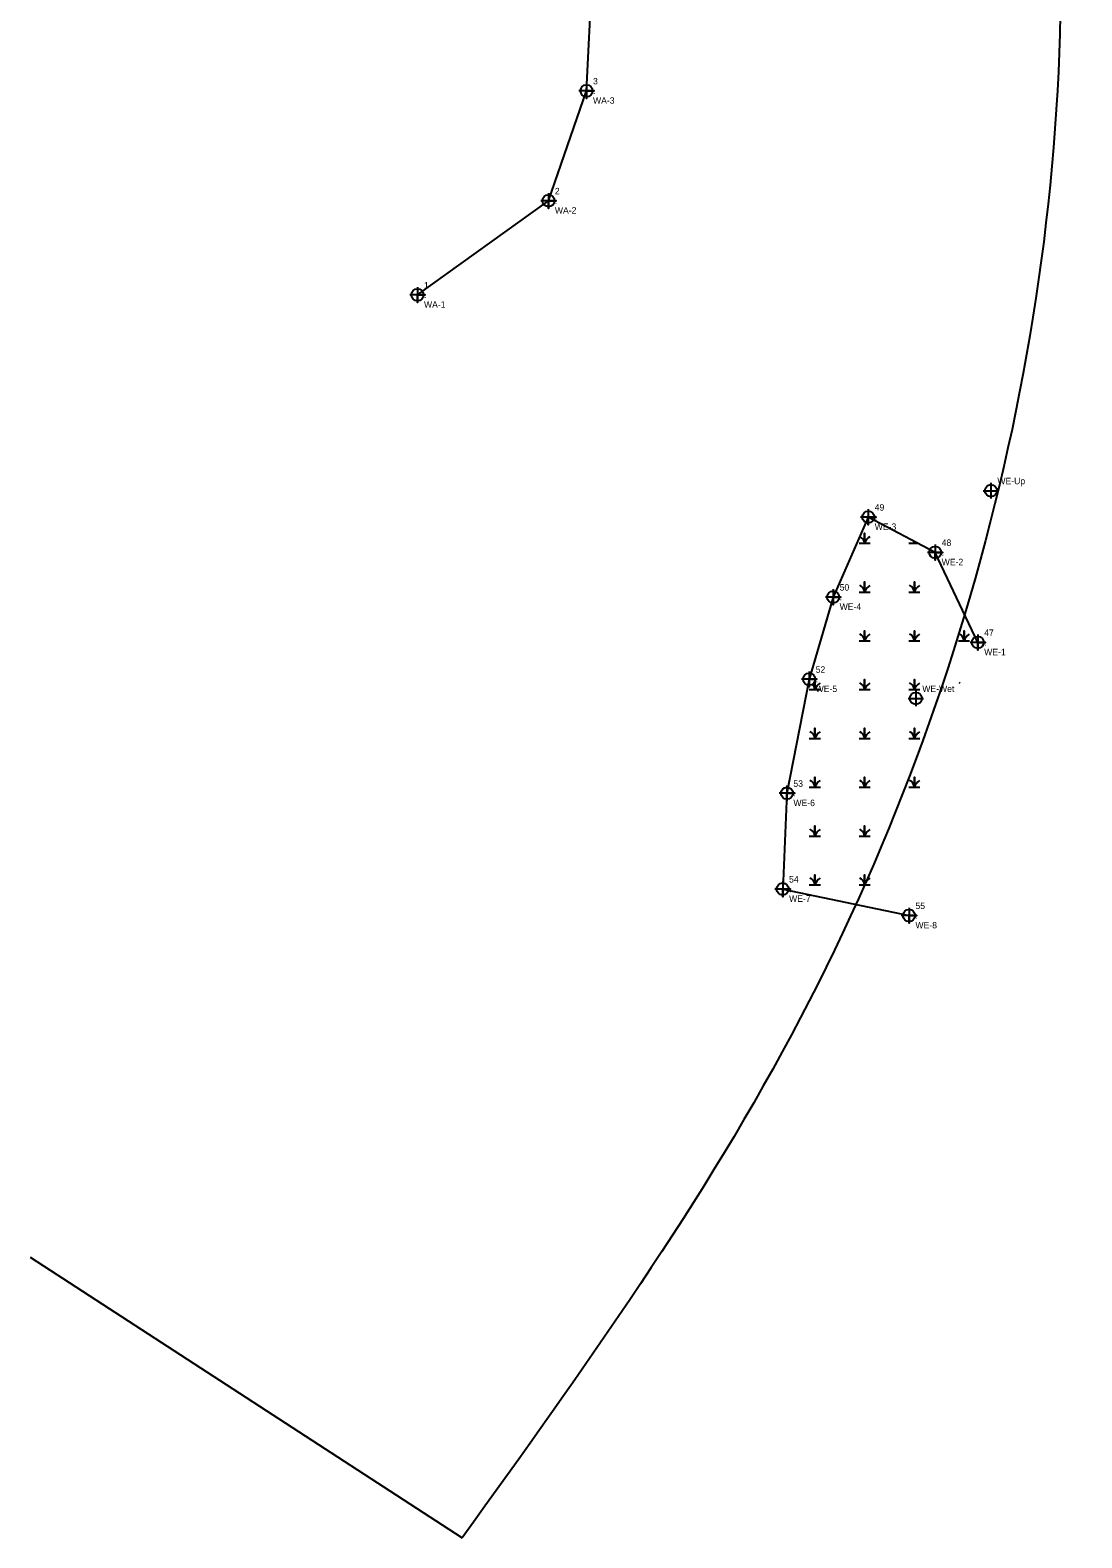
# Model space of a CAD drawing. Extents: x 1835303 to 1835785, y 366400 to 367935.
# Drawn here: x 1835303 to 1835711, y 366400 to 366986 of the extents above; entities that cross this region are included whole.
import ezdxf

# ---------------------------------------------------------------- set-up
doc = ezdxf.new("R2010")
doc.units = 0
for name, color, linetype in [('Cogo Default Point CELL', 7, 'Continuous'), ('COGO Default Point Number', 7, 'Continuous'), ('Default', 7, 'Continuous'), ('Exist Environmental Wetland Boundary', 7, 'Continuous'), ('Exist Environmental Wetland Boundary Cogo Comment', 7, 'Continuous'), ('Exist Environmental Wetland Boundary Cogo Elevation', 7, 'Continuous'), ('Exist Environmental Wetland Boundary Cogo Number', 7, 'Continuous'), ('Exist Environmental Wetland Boundary Cogo Point CELL', 7, 'Continuous'), ('Exist Hydro Jurisdictional Stream or Body of Water NEU Mitigable', 7, 'Continuous'), ('Exist Hydro Swamp or Marsh', 7, 'Continuous')]:
    doc.layers.add(name, color=color, linetype=linetype)

msp = doc.modelspace()

# ---------------------------------------------------------------- linework, layer by layer
at = {"layer": 'Cogo Default Point CELL'}
for points in [[(1835675.46, 366809.72), (1835675.46, 366806.72)], [(1835672.46, 366806.72), (1835675.46, 366806.72)], [(1835675.46, 366806.72), (1835678.46, 366806.72)], [(1835675.46, 366806.72), (1835675.46, 366803.72)], [(1835643.31, 366726.03), (1835646.31, 366726.03)], [(1835646.31, 366729.03), (1835646.31, 366726.03)], [(1835646.31, 366726.03), (1835649.31, 366726.03)], [(1835646.31, 366726.03), (1835646.31, 366723.03)]]:
    msp.add_lwpolyline(points, dxfattribs=at)
for centre in [(1835675.46, 366806.72), (1835646.31, 366726.03)]:
    msp.add_circle(centre, 2.34, dxfattribs=at)
at = {"layer": 'Default'}
msp.add_line((1835302.51, 366509.09), (1835470.17, 366400.05), dxfattribs=at)
msp.add_spline([(1835622.69, 367917.35), (1835610.42, 367781.31), (1835628.86, 367442.44), (1835700.95, 367057.13), (1835601.57, 366602.08), (1835470.17, 366400.05)], degree=3, dxfattribs=at)
at = {"layer": 'Exist Environmental Wetland Boundary'}
msp.add_lwpolyline([(1835670.33, 366747.81), (1835653.83, 366782.76), (1835627.85, 366796.48), (1835614.23, 366765.42), (1835604.91, 366733.5), (1835596.28, 366689.21), (1835594.61, 366652.02), (1835643.65, 366641.72)], dxfattribs=at)
at = {"layer": 'Exist Environmental Wetland Boundary Cogo Point CELL'}
for points in [[(1835518.49, 366965.01), (1835518.49, 366959.01), (1835518.49, 366962.01), (1835521.49, 366962.01), (1835515.49, 366962.01)], [(1835503.69, 366922.31), (1835503.69, 366916.31), (1835503.69, 366919.31), (1835506.69, 366919.31), (1835500.69, 366919.31)], [(1835452.88, 366885.76), (1835452.88, 366879.76), (1835452.88, 366882.76), (1835455.88, 366882.76), (1835449.88, 366882.76)], [(1835627.85, 366799.48), (1835627.85, 366793.48), (1835627.85, 366796.48), (1835630.85, 366796.48), (1835624.85, 366796.48)], [(1835653.83, 366785.76), (1835653.83, 366779.76), (1835653.83, 366782.76), (1835656.83, 366782.76), (1835650.83, 366782.76)], [(1835614.23, 366768.42), (1835614.23, 366762.42), (1835614.23, 366765.42), (1835617.23, 366765.42), (1835611.23, 366765.42)], [(1835670.33, 366750.81), (1835670.33, 366744.81), (1835670.33, 366747.81), (1835673.33, 366747.81), (1835667.33, 366747.81)], [(1835604.91, 366736.5), (1835604.91, 366730.5), (1835604.91, 366733.5), (1835607.91, 366733.5), (1835601.91, 366733.5)], [(1835596.28, 366692.21), (1835596.28, 366686.21), (1835596.28, 366689.21), (1835599.28, 366689.21), (1835593.28, 366689.21)], [(1835594.61, 366655.02), (1835594.61, 366649.02), (1835594.61, 366652.02), (1835597.61, 366652.02), (1835591.61, 366652.02)], [(1835643.65, 366644.72), (1835643.65, 366638.72), (1835643.65, 366641.72), (1835646.65, 366641.72), (1835640.65, 366641.72)]]:
    msp.add_lwpolyline(points, dxfattribs=at)
for centre in [(1835518.49, 366962.01), (1835503.69, 366919.31), (1835452.88, 366882.76), (1835627.85, 366796.48), (1835653.83, 366782.76), (1835614.23, 366765.42), (1835670.33, 366747.81), (1835604.91, 366733.5), (1835596.28, 366689.21), (1835594.61, 366652.02), (1835643.65, 366641.72)]:
    msp.add_circle(centre, 2.34, dxfattribs=at)
at = {"layer": 'Exist Hydro Jurisdictional Stream or Body of Water NEU Mitigable'}
msp.add_lwpolyline([(1835452.88, 366882.76), (1835503.69, 366919.31), (1835518.49, 366962.01), (1835520.69, 367005.91), (1835520.98, 367049.5), (1835516.67, 367090.93), (1835510.8, 367142.28), (1835496.63, 367190.32), (1835483.12, 367227.97), (1835474.1, 367269.94), (1835464.36, 367306.36), (1835443.97, 367336.69), (1835413.38, 367355.04), (1835384.27, 367375.76), (1835355.5, 367380.19)], dxfattribs=at)
at = {"layer": 'Exist Hydro Swamp or Marsh'}
for points in [[(1835624.26, 366786.29), (1835626.41, 366786.29), (1835626.41, 366790.24), (1835626.41, 366786.29), (1835628.56, 366786.29)], [(1835643.57, 366786.29), (1835645.72, 366786.29), (1835645.72, 366787.04)], [(1835645.72, 366787.04), (1835645.72, 366786.29), (1835647.14, 366786.29)], [(1835624.26, 366767.34), (1835626.41, 366767.34), (1835626.41, 366771.29), (1835626.41, 366767.34), (1835628.56, 366767.34)], [(1835643.57, 366767.34), (1835645.72, 366767.34), (1835645.72, 366771.29), (1835645.72, 366767.34), (1835647.87, 366767.34)], [(1835624.26, 366748.39), (1835626.41, 366748.39), (1835626.41, 366752.34), (1835626.41, 366748.39), (1835628.56, 366748.39)], [(1835643.57, 366748.39), (1835645.72, 366748.39), (1835645.72, 366752.34), (1835645.72, 366748.39), (1835647.87, 366748.39)], [(1835662.88, 366748.39), (1835665.03, 366748.39), (1835665.03, 366752.34), (1835665.03, 366748.39), (1835667.18, 366748.39)], [(1835604.94, 366729.44), (1835607.09, 366729.44), (1835607.09, 366732.69)], [(1835607.09, 366732.69), (1835607.09, 366729.44), (1835609.25, 366729.44)], [(1835624.26, 366729.44), (1835626.41, 366729.44), (1835626.41, 366733.39), (1835626.41, 366729.44), (1835628.56, 366729.44)], [(1835643.57, 366729.44), (1835645.72, 366729.44), (1835645.72, 366733.39), (1835645.72, 366729.44), (1835647.87, 366729.44)], [(1835604.94, 366710.49), (1835607.09, 366710.49), (1835607.09, 366714.44), (1835607.09, 366710.49), (1835609.25, 366710.49)], [(1835624.26, 366710.49), (1835626.41, 366710.49), (1835626.41, 366714.44), (1835626.41, 366710.49), (1835628.56, 366710.49)], [(1835643.57, 366710.49), (1835645.72, 366710.49), (1835645.72, 366714.44), (1835645.72, 366710.49), (1835647.87, 366710.49)], [(1835604.94, 366691.54), (1835607.09, 366691.54), (1835607.09, 366695.49), (1835607.09, 366691.54), (1835609.25, 366691.54)], [(1835624.26, 366691.54), (1835626.41, 366691.54), (1835626.41, 366695.49), (1835626.41, 366691.54), (1835628.56, 366691.54)], [(1835643.57, 366691.54), (1835645.72, 366691.54), (1835645.72, 366695.49), (1835645.72, 366691.54), (1835647.87, 366691.54)], [(1835604.94, 366672.59), (1835607.09, 366672.59), (1835607.09, 366676.54), (1835607.09, 366672.59), (1835609.25, 366672.59)], [(1835624.26, 366672.59), (1835626.41, 366672.59), (1835626.41, 366676.54), (1835626.41, 366672.59), (1835628.56, 366672.59)], [(1835604.94, 366653.64), (1835607.09, 366653.64), (1835607.09, 366657.59), (1835607.09, 366653.64), (1835609.25, 366653.64)], [(1835624.26, 366653.64), (1835626.41, 366653.64), (1835626.41, 366657.59), (1835626.41, 366653.64), (1835628.56, 366653.64)]]:
    msp.add_lwpolyline(points, dxfattribs=at)
for centre, radius, start, end in [((1835623.34, 366786.07), 3.07, 4.14034, 67.26678), ((1835630.97, 366784.78), 4.81, 122.12745, 161.62219), ((1835642.65, 366786.07), 3.07, 4.14034, 20.318), ((1835650.28, 366784.78), 4.81, 153.68473, 161.62219), ((1835623.34, 366767.12), 3.07, 4.14034, 67.53497), ((1835630.97, 366765.83), 4.81, 122.12745, 161.62219), ((1835642.65, 366767.12), 3.07, 4.14034, 67.53497), ((1835650.28, 366765.83), 4.81, 122.12745, 161.62219), ((1835623.34, 366748.17), 3.07, 4.14034, 67.53497), ((1835630.97, 366746.88), 4.81, 122.12745, 161.62219), ((1835642.65, 366748.17), 3.07, 4.14034, 67.53497), ((1835650.28, 366746.88), 4.81, 122.12745, 161.62219), ((1835661.97, 366748.17), 3.07, 4.14034, 67.53497), ((1835669.59, 366746.88), 4.81, 122.12745, 161.62219), ((1835611.66, 366727.93), 4.81, 122.12745, 161.62219), ((1835623.34, 366729.22), 3.07, 4.14034, 67.53497), ((1835630.97, 366727.93), 4.81, 122.12745, 161.62219), ((1835642.65, 366729.22), 3.07, 4.14034, 67.53497), ((1835650.28, 366727.93), 4.81, 122.12745, 161.62219), ((1835661.97, 366729.22), 3.07, 60.17264, 67.53497), ((1835604.03, 366729.22), 3.07, 4.14034, 48.15652), ((1835604.03, 366710.27), 3.07, 4.14034, 67.53497), ((1835611.66, 366708.98), 4.81, 122.12745, 161.62219), ((1835623.34, 366710.27), 3.07, 4.14034, 67.53497), ((1835630.97, 366708.98), 4.81, 122.12745, 161.62219), ((1835642.65, 366710.27), 3.07, 4.14034, 67.53497), ((1835650.28, 366708.98), 4.81, 122.12745, 161.62219), ((1835604.03, 366691.32), 3.07, 4.14034, 67.53497), ((1835611.66, 366690.03), 4.81, 122.12745, 161.62219), ((1835623.34, 366691.32), 3.07, 4.14034, 67.53497), ((1835630.97, 366690.03), 4.81, 122.12745, 161.62219), ((1835642.65, 366691.32), 3.07, 4.14034, 67.53497), ((1835650.28, 366690.03), 4.81, 122.12745, 161.62219), ((1835604.03, 366672.37), 3.07, 4.14034, 67.53497), ((1835611.66, 366671.08), 4.81, 122.12745, 161.62219), ((1835623.34, 366672.37), 3.07, 4.14034, 67.53497), ((1835630.97, 366671.08), 4.81, 122.12745, 161.62219), ((1835604.03, 366653.42), 3.07, 4.14034, 67.53497), ((1835611.66, 366652.13), 4.81, 122.12745, 161.62219), ((1835623.34, 366653.42), 3.07, 4.14034, 67.53497), ((1835630.97, 366652.13), 4.81, 122.12745, 161.62219)]:
    msp.add_arc(centre, radius, start, end, dxfattribs=at)

# ---------------------------------------------------------------- texts
at = {"layer": 'COGO Default Point Number'}
for s, p in [('WE-Up', (1835677.96, 366809.22)), ('WE-Wet', (1835648.81, 366728.53))]:
    msp.add_text(s, height=2.5, dxfattribs=at).set_placement(p)
at = {"layer": 'Exist Environmental Wetland Boundary Cogo Comment'}
for s, p in [('WA-3', (1835520.99, 366957.01)), ('WA-2', (1835506.19, 366914.31)), ('WA-1', (1835455.38, 366877.76)), ('WE-3', (1835630.35, 366791.48)), ('WE-2', (1835656.33, 366777.76)), ('WE-4', (1835616.73, 366760.42)), ('WE-1', (1835672.83, 366742.81)), ('WE-5', (1835607.41, 366728.5)), ('WE-6', (1835598.78, 366684.21)), ('WE-7', (1835597.11, 366647.03)), ('WE-8', (1835646.15, 366636.73))]:
    msp.add_text(s, height=2.5, dxfattribs=at).set_placement(p)
at = {"layer": 'Exist Environmental Wetland Boundary Cogo Elevation'}
for p in [(1835520.99, 366960.76), (1835506.19, 366918.06), (1835455.38, 366881.51), (1835630.35, 366795.23), (1835656.33, 366781.51), (1835616.73, 366764.17), (1835672.83, 366746.56), (1835607.41, 366732.25), (1835598.78, 366687.96), (1835597.11, 366650.78), (1835646.15, 366640.48)]:
    msp.add_text('.', height=2.5, dxfattribs=at).set_placement(p)
at = {"layer": 'Exist Environmental Wetland Boundary Cogo Number'}
for s, p in [('3', (1835520.99, 366964.51)), ('2', (1835506.19, 366921.81)), ('1', (1835455.38, 366885.26)), ('49', (1835630.35, 366798.98)), ('48', (1835656.33, 366785.26)), ('50', (1835616.73, 366767.92)), ('47', (1835672.83, 366750.31)), ('52', (1835607.41, 366736)), ('53', (1835598.78, 366691.71)), ('54', (1835597.11, 366654.53)), ('55', (1835646.15, 366644.23))]:
    msp.add_text(s, height=2.5, dxfattribs=at).set_placement(p)

doc.saveas('drawing.dxf')
